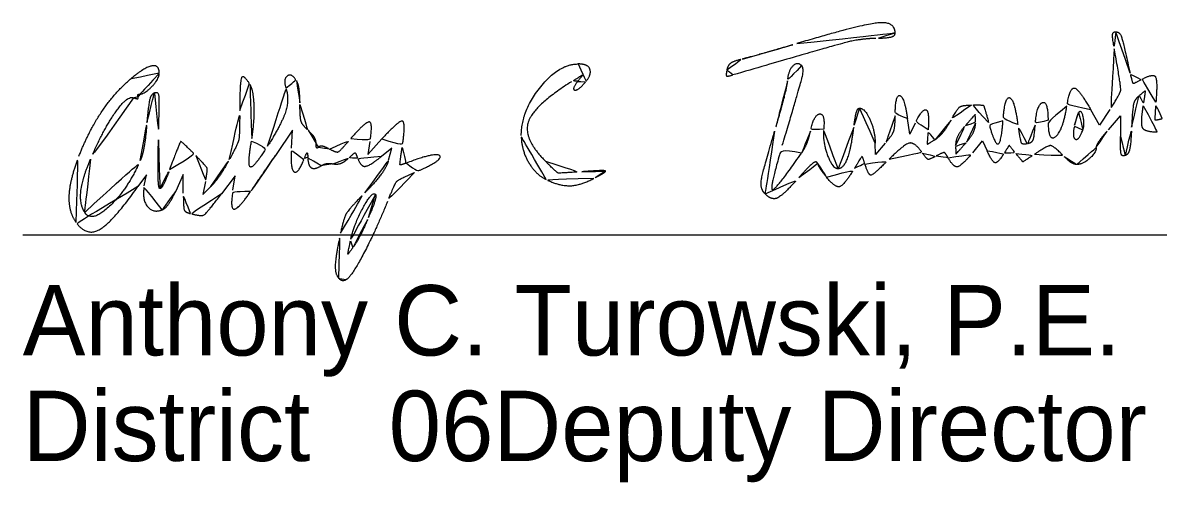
# Model space of a CAD drawing. Extents: x 208586767.6 to 208586821.4, y -134301046.9 to -134301022.9.
# Drawn here: x 208586817.913 to 208586820.172, y -134301042.756 to -134301041.841 of the extents above; entities that cross this region are included whole.
import ezdxf

# ---------------------------------------------------------------- set-up
doc = ezdxf.new("R2010")
doc.units = 0
doc.layers.add('SH_Data', color=7, linetype='Continuous')
doc.layers.add('SH_Text', color=7, linetype='Continuous')

msp = doc.modelspace()

# ---------------------------------------------------------------- linework, layer by layer
at = {"layer": 'SH_Data'}
msp.add_line((208586817.9133, -134301042.2635), (208586821.4133, -134301042.2635), dxfattribs=at)
at = {"layer": 'SH_Text'}
for p, q in [((208586819.3142, -134301041.9351), (208586819.3142, -134301041.9351)), ((208586818.9544, -134301042.1534), (208586818.9544, -134301042.1534)), ((208586818.601, -134301042.2292), (208586818.601, -134301042.2292)), ((208586818.5425, -134301042.3503), (208586818.5425, -134301042.3503))]:
    msp.add_line(p, q, dxfattribs=at)
for points in [[(208586819.6887, -134301042.0413), (208586819.6778, -134301042.0635), (208586819.6734, -134301042.0321)], [(208586820.0759, -134301042.0144), (208586820.0553, -134301042.0456), (208586820.0379, -134301042.0146)], [(208586820.073, -134301042.0543), (208586820.097, -134301042.0269), (208586820.097, -134301042.0679)], [(208586818.4478, -134301042.0909), (208586818.4502, -134301042.0555), (208586818.4174, -134301042.1035)], [(208586818.6042, -134301042.0778), (208586818.5999, -134301042.1035), (208586818.6279, -134301042.0727)], [(208586819.6292, -134301042.081), (208586819.6095, -134301042.1035), (208586819.6092, -134301042.0811)], [(208586819.8032, -134301042.1001), (208586819.8229, -134301042.0767), (208586819.8318, -134301042.0961)], [(208586818.6411, -134301042.1151), (208586818.6479, -134301042.0911), (208586818.6274, -134301042.1073)], [(208586818.1552, -134301042.1659), (208586818.1594, -134301042.1438), (208586818.1425, -134301042.1676)], [(208586818.2328, -134301042.1805), (208586818.2326, -134301042.1435), (208586818.2177, -134301042.1763)], [(208586818.3315, -134301042.1749), (208586818.3361, -134301042.1462), (208586818.3087, -134301042.1821)], [(208586818.2769, -134301042.1572), (208586818.2714, -134301042.1835), (208586818.2875, -134301042.1675)]]:
    msp.add_lwpolyline(points, dxfattribs=at)
for points in [[(208586819.4532, -134301041.883), (208586819.5786, -134301041.8456), (208586819.649, -134301041.8382), (208586819.6489, -134301041.8624)], [(208586819.6107, -134301041.8726), (208586819.5788, -134301041.8736), (208586819.526, -134301041.8871), (208586819.3261, -134301041.9454)], [(208586819.6489, -134301041.8624), (208586819.6489, -134301041.8677), (208586819.6332, -134301041.8719), (208586819.6107, -134301041.8726)], [(208586820.0876, -134301041.8595), (208586820.0818, -134301041.8595), (208586820.0809, -134301041.8706), (208586820.0849, -134301041.8935)], [(208586820.1163, -134301041.9417), (208586820.102, -134301041.8779), (208586820.0955, -134301041.8595), (208586820.0876, -134301041.8595)], [(208586819.345, -134301041.9137), (208586819.3604, -134301041.9099), (208586819.4091, -134301041.8961), (208586819.4532, -134301041.883)], [(208586820.0849, -134301041.8935), (208586820.0983, -134301041.9683), (208586820.0972, -134301041.9823), (208586820.0759, -134301042.0144)], [(208586818.9051, -134301042.0658), (208586818.9056, -134301042.0167), (208586818.98, -134301041.9235), (208586819.0186, -134301041.9235)], [(208586819.0186, -134301041.9235), (208586819.0376, -134301041.9235), (208586819.0457, -134301041.9441), (208586819.0329, -134301041.9596)], [(208586819.3142, -134301041.9351), (208586819.3159, -134301041.9261), (208586819.3276, -134301041.9179), (208586819.345, -134301041.9137)], [(208586819.4628, -134301041.9266), (208586819.454, -134301041.9179), (208586819.4367, -134301041.9369), (208586819.435, -134301041.9571)], [(208586818.1291, -134301041.9525), (208586818.156, -134301041.93), (208586818.185, -134301041.9246), (208586818.185, -134301041.9422)], [(208586818.185, -134301041.9422), (208586818.185, -134301041.9529), (208586818.1561, -134301041.9835), (208586818.1461, -134301041.9835)], [(208586818.437, -134301041.9718), (208586818.4313, -134301041.9535), (208586818.448, -134301041.9411), (208586818.4577, -134301041.9565)], [(208586819.018, -134301041.9576), (208586819.0276, -134301041.9455), (208586819.0259, -134301041.9457), (208586819.005, -134301041.9589)], [(208586819.3261, -134301041.9454), (208586819.315, -134301041.9487), (208586819.312, -134301041.9461), (208586819.3142, -134301041.9351)], [(208586819.4244, -134301042.0853), (208586819.4591, -134301041.9698), (208586819.4682, -134301041.9321), (208586819.4628, -134301041.9266)], [(208586820.138, -134301041.9549), (208586820.1233, -134301041.9628), (208586820.1208, -134301041.9612), (208586820.1163, -134301041.9417)], [(208586818.0251, -134301042.1071), (208586818.0453, -134301042.0559), (208586818.0962, -134301041.9803), (208586818.1291, -134301041.9525)], [(208586818.345, -134301042.0159), (208586818.345, -134301041.96), (208586818.352, -134301041.9425), (208586818.3655, -134301041.9644)], [(208586818.3655, -134301041.9644), (208586818.373, -134301041.9765), (208586818.3747, -134301042.0409), (208586818.3684, -134301042.0769)], [(208586818.4577, -134301041.9565), (208586818.4616, -134301041.9625), (208586818.4648, -134301041.984), (208586818.4648, -134301042.0042)], [(208586819.005, -134301041.9589), (208586818.9297, -134301042.0065), (208586818.9082, -134301042.072), (208586818.9533, -134301042.117)], [(208586819.0329, -134301041.9596), (208586819.0189, -134301041.9764), (208586819.0046, -134301041.9745), (208586819.018, -134301041.9576)], [(208586819.435, -134301041.9571), (208586819.4341, -134301041.9674), (208586819.4225, -134301042.0125), (208586819.4092, -134301042.0574)], [(208586820.1677, -134301041.9992), (208586820.1712, -134301041.9555), (208586820.1621, -134301041.942), (208586820.138, -134301041.9549)], [(208586818.1339, -134301041.9907), (208586818.1214, -134301041.9859), (208586818.0735, -134301042.0542), (208586818.0484, -134301042.1128)], [(208586818.1429, -134301041.9892), (208586818.1439, -134301041.9923), (208586818.1399, -134301041.993), (208586818.1339, -134301041.9907)], [(208586818.1461, -134301041.9835), (208586818.1433, -134301041.9835), (208586818.1418, -134301041.986), (208586818.1429, -134301041.9892)], [(208586818.1604, -134301042.0401), (208586818.1633, -134301042.0049), (208586818.1688, -134301041.9835), (208586818.1754, -134301041.9813)], [(208586818.1754, -134301041.9813), (208586818.1838, -134301041.9785), (208586818.1854, -134301041.9976), (208586818.1834, -134301042.0747)], [(208586818.4005, -134301042.087), (208586818.4286, -134301042.0426), (208586818.4441, -134301041.9939), (208586818.437, -134301041.9718)], [(208586819.6734, -134301042.0321), (208586819.6672, -134301041.9886), (208586819.649, -134301041.9843), (208586819.649, -134301042.0264)], [(208586819.893, -134301042.0439), (208586819.886, -134301041.9929), (208586819.867, -134301041.9884), (208586819.8634, -134301042.0369)], [(208586820.0379, -134301042.0146), (208586820.0144, -134301041.9728), (208586819.9965, -134301041.9702), (208586819.9904, -134301042.0078)], [(208586820.1193, -134301042.0495), (208586820.1209, -134301042.0129), (208586820.1256, -134301041.9936), (208586820.1346, -134301041.9862)], [(208586820.1346, -134301041.9862), (208586820.1463, -134301041.9765), (208586820.1471, -134301041.9786), (208586820.1425, -134301042.007)], [(208586818.4648, -134301042.0042), (208586818.4649, -134301042.0307), (208586818.4694, -134301042.045), (208586818.481, -134301042.0555)], [(208586819.5779, -134301042.0115), (208586819.5742, -134301042.0115), (208586819.5691, -134301042.0287), (208586819.5666, -134301042.0498)], [(208586819.6092, -134301042.0811), (208586819.6089, -134301042.0567), (208586819.5886, -134301042.0115), (208586819.5779, -134301042.0115)], [(208586819.8009, -134301042.0052), (208586819.7816, -134301042.0058), (208586819.7732, -134301042.0119), (208586819.7602, -134301042.0351)], [(208586819.8348, -134301042.0401), (208586819.8261, -134301042.0076), (208586819.8232, -134301042.0046), (208586819.8009, -134301042.0052)], [(208586819.953, -134301042.0355), (208586819.953, -134301041.996), (208586819.9304, -134301042.0048), (208586819.9274, -134301042.0454)], [(208586819.9904, -134301042.0078), (208586819.9824, -134301042.0575), (208586819.953, -134301042.0792), (208586819.953, -134301042.0355)], [(208586820.1425, -134301042.007), (208586820.1367, -134301042.043), (208586820.1463, -134301042.0595), (208586820.1731, -134301042.0595)], [(208586820.1804, -134301042.0322), (208586820.1663, -134301042.036), (208586820.165, -134301042.0328), (208586820.1677, -134301041.9992)], [(208586818.3243, -134301042.1139), (208586818.3414, -134301042.0829), (208586818.345, -134301042.0659), (208586818.345, -134301042.0159)], [(208586819.5067, -134301042.0531), (208586819.51, -134301042.0213), (208586819.4869, -134301042.0249), (208586819.4803, -134301042.0573)], [(208586819.649, -134301042.0264), (208586819.649, -134301042.0492), (208586819.6432, -134301042.0651), (208586819.6292, -134301042.081)], [(208586819.7146, -134301042.0546), (208586819.7175, -134301042.0185), (208586819.7036, -134301042.0113), (208586819.6887, -134301042.0413)], [(208586819.7602, -134301042.0351), (208586819.7511, -134301042.0512), (208586819.7366, -134301042.0688), (208586819.728, -134301042.0742)], [(208586819.7887, -134301042.0459), (208586819.8076, -134301042.0245), (208586819.8085, -134301042.0242), (208586819.8087, -134301042.041)], [(208586820.0059, -134301042.0455), (208586820.0088, -134301042.0334), (208586820.0124, -134301042.0221), (208586820.0139, -134301042.0203)], [(208586820.0139, -134301042.0203), (208586820.0195, -134301042.0138), (208586820.0265, -134301042.044), (208586820.0221, -134301042.0555)], [(208586818.1472, -134301042.1155), (208586818.152, -134301042.1045), (208586818.158, -134301042.0706), (208586818.1604, -134301042.0401)], [(208586818.481, -134301042.0555), (208586818.4898, -134301042.0634), (208586818.497, -134301042.0754), (208586818.497, -134301042.082)], [(208586818.5661, -134301042.0719), (208586818.5955, -134301042.0378), (208586818.6104, -134301042.0401), (208586818.6042, -134301042.0778)], [(208586818.6279, -134301042.0727), (208586818.6627, -134301042.0345), (208586818.6757, -134301042.0399), (208586818.6682, -134301042.0895)], [(208586819.4092, -134301042.0574), (208586819.3851, -134301042.1384), (208586819.38, -134301042.1719), (208586819.3903, -134301042.1821)], [(208586819.4803, -134301042.0573), (208586819.4774, -134301042.0715), (208586819.4693, -134301042.0913), (208586819.4624, -134301042.1013)], [(208586819.5353, -134301042.1315), (208586819.524, -134301042.1315), (208586819.5042, -134301042.0771), (208586819.5067, -134301042.0531)], [(208586819.5666, -134301042.0498), (208586819.5617, -134301042.0919), (208586819.5464, -134301042.1315), (208586819.5353, -134301042.1315)], [(208586819.728, -134301042.0742), (208586819.7132, -134301042.0834), (208586819.7123, -134301042.0822), (208586819.7146, -134301042.0546)], [(208586819.7692, -134301042.0859), (208586819.7691, -134301042.0763), (208586819.7778, -134301042.0583), (208586819.7887, -134301042.0459)], [(208586819.8087, -134301042.041), (208586819.8088, -134301042.0507), (208586819.8001, -134301042.0687), (208586819.7892, -134301042.081)], [(208586819.8634, -134301042.0369), (208586819.8601, -134301042.082), (208586819.8464, -134301042.0835), (208586819.8348, -134301042.0401)], [(208586819.9118, -134301042.0818), (208586819.9015, -134301042.0838), (208586819.8974, -134301042.0755), (208586819.893, -134301042.0439)], [(208586819.9274, -134301042.0454), (208586819.9257, -134301042.0693), (208586819.921, -134301042.0801), (208586819.9118, -134301042.0818)], [(208586820.0221, -134301042.0555), (208586820.0138, -134301042.0771), (208586820.0003, -134301042.0687), (208586820.0059, -134301042.0455)], [(208586820.049, -134301042.0893), (208586820.049, -134301042.0851), (208586820.0598, -134301042.0693), (208586820.073, -134301042.0543)], [(208586820.107, -134301042.1055), (208586820.1133, -134301042.1034), (208586820.1178, -134301042.0828), (208586820.1193, -134301042.0495)], [(208586818.1834, -134301042.0747), (208586818.1821, -134301042.1279), (208586818.1834, -134301042.1715), (208586818.1863, -134301042.1715)], [(208586818.2056, -134301042.1335), (208586818.2256, -134301042.0791), (208586818.2296, -134301042.077), (208586818.2576, -134301042.1057)], [(208586818.3684, -134301042.0769), (208586818.3598, -134301042.1265), (208586818.3728, -134301042.1305), (208586818.4005, -134301042.087)], [(208586818.5236, -134301042.0929), (208586818.538, -134301042.1006), (208586818.5437, -134301042.0978), (208586818.5661, -134301042.0719)], [(208586818.9544, -134301042.1534), (208586818.9331, -134301042.1432), (208586818.9049, -134301042.093), (208586818.9051, -134301042.0658)], [(208586819.6372, -134301042.1128), (208586819.6672, -134301042.0828), (208586819.688, -134301042.079), (208586819.7034, -134301042.1008)], [(208586819.7892, -134301042.081), (208586819.7703, -134301042.1025), (208586819.7694, -134301042.1027), (208586819.7692, -134301042.0859)], [(208586820.097, -134301042.0679), (208586820.097, -134301042.097), (208586820.0998, -134301042.1079), (208586820.107, -134301042.1055)], [(208586818.4174, -134301042.1035), (208586818.3994, -134301042.1299), (208586818.3766, -134301042.163), (208586818.3668, -134301042.1772)], [(208586818.4725, -134301042.1141), (208586818.4602, -134301042.1448), (208586818.4451, -134301042.1306), (208586818.4478, -134301042.0909)], [(208586818.4804, -134301042.109), (208586818.4801, -134301042.0995), (208586818.4777, -134301042.1011), (208586818.4725, -134301042.1141)], [(208586818.497, -134301042.082), (208586818.497, -134301042.0887), (208586818.4992, -134301042.0919), (208586818.502, -134301042.0891)], [(208586818.502, -134301042.0891), (208586818.5048, -134301042.0863), (208586818.5145, -134301042.088), (208586818.5236, -134301042.0929)], [(208586818.5797, -134301042.1111), (208586818.5755, -134301042.1001), (208586818.5734, -134301042.1002), (208586818.5606, -134301042.1117)], [(208586818.6682, -134301042.0895), (208586818.6634, -134301042.122), (208586818.6643, -134301042.1254), (208586818.6766, -134301042.1207)], [(208586818.6766, -134301042.1207), (208586818.7361, -134301042.0979), (208586818.7504, -134301042.1148), (208586818.6926, -134301042.1396)], [(208586819.4624, -134301042.1013), (208586819.4103, -134301042.176), (208586819.3987, -134301042.1711), (208586819.4244, -134301042.0853)], [(208586819.7034, -134301042.1008), (208586819.712, -134301042.1128), (208586819.717, -134301042.1139), (208586819.7306, -134301042.1066)], [(208586819.7306, -134301042.1066), (208586819.744, -134301042.0994), (208586819.7487, -134301042.1002), (208586819.7545, -134301042.1106)], [(208586819.7545, -134301042.1106), (208586819.7652, -134301042.1297), (208586819.7811, -134301042.1263), (208586819.8032, -134301042.1001)], [(208586819.8318, -134301042.0961), (208586819.8424, -134301042.1194), (208586819.8535, -134301042.1208), (208586819.8663, -134301042.1003)], [(208586819.8663, -134301042.1003), (208586819.8755, -134301042.0856), (208586819.8761, -134301042.0856), (208586819.8893, -134301042.1019)], [(208586819.8893, -134301042.1019), (208586819.9028, -134301042.1185), (208586819.9031, -134301042.1185), (208586819.9259, -134301042.1033)], [(208586819.9259, -134301042.1033), (208586819.9526, -134301042.0855), (208586819.9639, -134301042.0864), (208586819.9854, -134301042.1079)], [(208586820.0103, -134301042.1235), (208586820.022, -134301042.1235), (208586820.049, -134301042.0996), (208586820.049, -134301042.0893)], [(208586818.0197, -134301042.2391), (208586818.004, -134301042.2176), (208586818.0066, -134301042.1541), (208586818.0251, -134301042.1071)], [(208586818.0484, -134301042.1128), (208586818.0319, -134301042.1512), (208586818.0262, -134301042.2021), (208586818.0366, -134301042.2189)], [(208586818.0366, -134301042.2189), (208586818.0499, -134301042.2404), (208586818.1224, -134301042.1726), (208586818.1472, -134301042.1155)], [(208586818.2576, -134301042.1057), (208586818.2787, -134301042.1273), (208586818.2815, -134301042.1348), (208586818.2769, -134301042.1572)], [(208586818.2875, -134301042.1675), (208586818.2964, -134301042.1587), (208586818.3129, -134301042.1346), (208586818.3243, -134301042.1139)], [(208586818.507, -134301042.1261), (208586818.4939, -134301042.1343), (208586818.4811, -134301042.126), (208586818.4804, -134301042.109)], [(208586818.5316, -134301042.1223), (208586818.5236, -134301042.121), (208586818.5125, -134301042.1227), (208586818.507, -134301042.1261)], [(208586818.5606, -134301042.1117), (208586818.5528, -134301042.1189), (208586818.5397, -134301042.1236), (208586818.5316, -134301042.1223)], [(208586818.6274, -134301042.1073), (208586818.6028, -134301042.1266), (208586818.5862, -134301042.128), (208586818.5797, -134301042.1111)], [(208586818.5941, -134301042.1798), (208586818.6161, -134301042.1575), (208586818.6373, -134301042.1283), (208586818.6411, -134301042.1151)], [(208586818.9533, -134301042.117), (208586818.976, -134301042.1398), (208586818.9807, -134301042.1411), (208586819.0253, -134301042.1379)], [(208586819.4574, -134301042.1495), (208586819.4772, -134301042.1271), (208586819.4926, -134301042.1156), (208586819.4947, -134301042.1214)], [(208586819.4947, -134301042.1214), (208586819.4966, -134301042.1268), (208586819.5046, -134301042.1391), (208586819.5123, -134301042.1487)], [(208586819.5681, -134301042.1309), (208586819.5824, -134301042.1074), (208586819.5837, -134301042.1069), (208586819.5887, -134301042.1227)], [(208586819.5887, -134301042.1227), (208586819.5961, -134301042.1459), (208586819.6062, -134301042.1438), (208586819.6372, -134301042.1128)], [(208586819.9854, -134301042.1079), (208586819.994, -134301042.1165), (208586820.0052, -134301042.1235), (208586820.0103, -134301042.1235)], [(208586818.1863, -134301042.1715), (208586818.1892, -134301042.1715), (208586818.1979, -134301042.1544), (208586818.2056, -134301042.1335)], [(208586818.6926, -134301042.1396), (208586818.6611, -134301042.1531), (208586818.6538, -134301042.161), (208586818.639, -134301042.1974)], [(208586819.0253, -134301042.1379), (208586819.0515, -134301042.136), (208586819.073, -134301042.1355), (208586819.073, -134301042.1368)], [(208586819.073, -134301042.1368), (208586819.073, -134301042.138), (208586819.0623, -134301042.1446), (208586819.0493, -134301042.1513)], [(208586819.5123, -134301042.1487), (208586819.5299, -134301042.1704), (208586819.5475, -134301042.1647), (208586819.5681, -134301042.1309)], [(208586818.1425, -134301042.1676), (208586818.0928, -134301042.2375), (208586818.0407, -134301042.2678), (208586818.0197, -134301042.2391)], [(208586818.1906, -134301042.2137), (208586818.1718, -134301042.2209), (208586818.1502, -134301042.1919), (208586818.1552, -134301042.1659)], [(208586819.0493, -134301042.1513), (208586819.0221, -134301042.1654), (208586818.9811, -134301042.1663), (208586818.9544, -134301042.1534)], [(208586819.3903, -134301042.1821), (208586819.4036, -134301042.1955), (208586819.4262, -134301042.1845), (208586819.4574, -134301042.1495)], [(208586818.2177, -134301042.1763), (208586818.2095, -134301042.1943), (208586818.1973, -134301042.2111), (208586818.1906, -134301042.2137)], [(208586818.247, -134301042.2212), (208586818.2362, -134301042.2184), (208586818.2329, -134301042.209), (208586818.2328, -134301042.1805)], [(208586818.3087, -134301042.1821), (208586818.2795, -134301042.2204), (208586818.2691, -134301042.227), (208586818.247, -134301042.2212)], [(208586818.3668, -134301042.1772), (208586818.342, -134301042.2129), (208586818.3255, -134301042.2118), (208586818.3315, -134301042.1749)], [(208586818.5455, -134301042.2604), (208586818.5522, -134301042.2292), (208586818.5628, -134301042.2116), (208586818.5941, -134301042.1798)], [(208586818.615, -134301042.1829), (208586818.6084, -134301042.1762), (208586818.5714, -134301042.245), (208586818.5652, -134301042.2755)], [(208586818.601, -134301042.2292), (208586818.611, -134301042.206), (208586818.6173, -134301042.1851), (208586818.615, -134301042.1829)], [(208586818.639, -134301042.1974), (208586818.6138, -134301042.2591), (208586818.5653, -134301042.35), (208586818.556, -134301042.3531)], [(208586818.5712, -134301042.2875), (208586818.5777, -134301042.2787), (208586818.5911, -134301042.2525), (208586818.601, -134301042.2292)], [(208586818.5425, -134301042.3503), (208586818.5345, -134301042.3423), (208586818.5357, -134301042.3061), (208586818.5455, -134301042.2604)], [(208586818.5652, -134301042.2755), (208586818.56, -134301042.3014), (208586818.5604, -134301042.3023), (208586818.5712, -134301042.2875)], [(208586818.556, -134301042.3531), (208586818.5516, -134301042.3546), (208586818.5455, -134301042.3533), (208586818.5425, -134301042.3503)]]:
    msp.add_open_spline(points, degree=2, dxfattribs=at)

# ---------------------------------------------------------------- texts
for s, p in [('Anthony C. Turowski, P.E.', (208586817.9133, -134301042.5035)), ('District       Deputy Director', (208586817.9133, -134301042.7135)), ('              06', (208586817.9133, -134301042.7135))]:
    msp.add_text(s, height=0.14, dxfattribs=at).set_placement(p)

doc.saveas('drawing.dxf')
